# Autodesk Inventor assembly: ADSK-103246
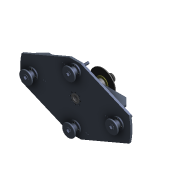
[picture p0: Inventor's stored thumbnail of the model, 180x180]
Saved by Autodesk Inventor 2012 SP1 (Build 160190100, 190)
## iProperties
Shininess: 0.0
Created: 2000-12
Part Number: ADSK-103246
Document SubType Name: Assembly
Designer: gao
Stock Number: ADSK-103246
Density: 0.0
Volumn: 0.0
Area: 0.0
PropertySet Name: Model Information
Control State: 0
Master: False
Checked Out: False
Author: gao
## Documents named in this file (9)
- D:\AOTC\Autodesk Inventor 2012 Essential for New Users\Autodesk Inventor 2012 Essentials - Project Files\Learning\Workspace\Sub-Assemblies\ADSK-103246.iam
- D:\AOTC\Autodesk Inventor 2012 Essential for New Users\Autodesk Inventor 2012 Essentials - Project Files\Learning\Workspace\Parts\ADSK-103455.ipt
- D:\AOTC\Autodesk Inventor 2012 Essential for New Users\Autodesk Inventor 2012 Essentials - Project Files\Learning\Workspace\Parts\ADSK-104069.ipt
- D:\AOTC\Autodesk Inventor 2012 Essential for New Users\Autodesk Inventor 2012 Essentials - Project Files\Learning\Workspace\Parts\ADSK-104065.ipt
- D:\AOTC\Autodesk Inventor 2012 Essential for New Users\Autodesk Inventor 2012 Essentials - Project Files\Learning\Workspace\Sub-Assemblies\ADSK-103223.iam
- D:\AOTC\Autodesk Inventor 2012 Essential for New Users\Autodesk Inventor 2012 Essentials - Project Files\Learning\Workspace\Sub-Assemblies\ADSK-103198.iam
- D:\AOTC\Autodesk Inventor 2012 Essential for New Users\Autodesk Inventor 2012 Essentials - Project Files\Learning\Workspace\Libraries\Content Center Files\en-US\4746AD94-7A15-4D0E-79EA-365386ECB28E.ipt
- D:\AOTC\Autodesk Inventor 2012 Essential for New Users\Autodesk Inventor 2012 Essentials - Project Files\Learning\Workspace\Parts\45665CD9-1C60-DBCA-D3BB-54EB80893890.ipt
- D:\AOTC\Autodesk Inventor 2012 Essential for New Users\Autodesk Inventor 2012 Essentials - Project Files\Learning\Workspace\Parts\F3808AAD-BDC4-3728-F238-65C25E68102C.ipt
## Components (48 placed, 8 different names)
1. ADSK-104069:1 — Insert:1, Insert:2, Insert:3, Insert:4, Insert:5, Insert:24, Insert:25, Insert:26, Insert:27, Insert:28, Insert:29, Insert:30, Insert:31
2. ADSK-103455:1 — Insert:1, Insert:17, Insert:18, Insert:19, Insert:20
3. ADSK-103455:2 — Insert:2, Insert:13, Insert:14, Insert:15, Insert:16
4. ADSK-103455:3 — Insert:3, Insert:9, Insert:10, Insert:11, Insert:12
5. ADSK-103455:4 — Insert:4, Insert:21, Insert:22, Insert:23
6. ADSK-104065:1 — Insert:5, Insert:6, Insert:7
7. ADSK-103223:1 [sub-assembly] — Insert:6
8. ADSK-103198:1 [sub-assembly] — Insert:7
9. Hex Cap Screw - 3/8 - 16 - 1 1/2:1
10. Hex Cap Screw - 3/8 - 16 - 1 1/2:2
11. Hex Cap Screw - 3/8 - 16 - 1 1/2:3 — Insert:22
12. Hex Cap Screw - 3/8 - 16 - 1 1/2:4 — Insert:8
13. Hex Cap Screw - 3/8 - 16 - 1 1/2:5
14. Hex Cap Screw - 3/8 - 16 - 1 1/2:6 — Insert:19
15. Hex Cap Screw - 3/8 - 16 - 1 1/2:7
16. Hex Cap Screw - 3/8 - 16 - 1 1/2:8 — Insert:17
17. Hex Cap Screw - 3/8 - 16 - 1 1/2:9
18. Hex Cap Screw - 3/8 - 16 - 1 1/2:10
19. Hex Cap Screw - 3/8 - 16 - 1 1/2:11
20. Hex Cap Screw - 3/8 - 16 - 1 1/2:12
21. Hex Cap Screw - 3/8 - 16 - 1 1/2:13
22. Hex Cap Screw - 3/8 - 16 - 1 1/2:14
23. Hex Cap Screw - 3/8 - 16 - 1 1/2:15
24. Hex Cap Screw - 3/8 - 16 - 1 1/2:16
25. Helical Spring Lock Washer - 3/8  Regular. Carbon Steel:1 — Insert:20
26. Helical Spring Lock Washer - 3/8  Regular. Carbon Steel:2
27. Helical Spring Lock Washer - 3/8  Regular. Carbon Steel:3 — Insert:18
28. Helical Spring Lock Washer - 3/8  Regular. Carbon Steel:4
29. Helical Spring Lock Washer - 3/8  Regular. Carbon Steel:5 — Insert:21
30. Helical Spring Lock Washer - 3/8  Regular. Carbon Steel:6 — Insert:23
31. Helical Spring Lock Washer - 3/8  Regular. Carbon Steel:7
32. Helical Spring Lock Washer - 3/8  Regular. Carbon Steel:8 — Insert:8
33. Helical Spring Lock Washer - 3/8  Regular. Carbon Steel:9 — Insert:12
34. Helical Spring Lock Washer - 3/8  Regular. Carbon Steel:10 — Insert:11
35. Helical Spring Lock Washer - 3/8  Regular. Carbon Steel:11 — Insert:9
36. Helical Spring Lock Washer - 3/8  Regular. Carbon Steel:12 — Insert:10
37. Helical Spring Lock Washer - 3/8  Regular. Carbon Steel:13 — Insert:13
38. Helical Spring Lock Washer - 3/8  Regular. Carbon Steel:14 — Insert:14
39. Helical Spring Lock Washer - 3/8  Regular. Carbon Steel:15 — Insert:16
40. Helical Spring Lock Washer - 3/8  Regular. Carbon Steel:16 — Insert:15
41. Hexagon Socket Head Cap Screw - 3/8 - 16 - 1 1/2:1 — Insert:30
42. Hexagon Socket Head Cap Screw - 3/8 - 16 - 1 1/2:2 — Insert:29
43. Hexagon Socket Head Cap Screw - 3/8 - 16 - 1 1/2:3 — Insert:28
44. Hexagon Socket Head Cap Screw - 3/8 - 16 - 1 1/2:4 — Insert:24
45. Hexagon Socket Head Cap Screw - 3/8 - 16 - 1 1/2:5 — Insert:25
46. Hexagon Socket Head Cap Screw - 3/8 - 16 - 1 1/2:6 — Insert:26
47. Hexagon Socket Head Cap Screw - 3/8 - 16 - 1 1/2:7 — Insert:27
48. Hexagon Socket Head Cap Screw - 3/8 - 16 - 1 1/2:8 — Insert:31
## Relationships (31: Insert 31)
- Insert:1: ADSK-104069:1 ↔ ADSK-103455:1
- Insert:2: ADSK-104069:1 ↔ ADSK-103455:2
- Insert:3: ADSK-104069:1 ↔ ADSK-103455:3
- Insert:4: ADSK-104069:1 ↔ ADSK-103455:4
- Insert:5: ADSK-104069:1 ↔ ADSK-104065:1
- Insert:6: ADSK-104065:1 ↔ ADSK-103223:1
- Insert:7: ADSK-104065:1 ↔ ADSK-103198:1
- Insert:8: Hex Cap Screw - 3/8 - 16 - 1 1/2:4 ↔ Helical Spring Lock Washer - 3/8  Regular. Carbon Steel:8
- Insert:9: ADSK-103455:3 ↔ Helical Spring Lock Washer - 3/8  Regular. Carbon Steel:11
- Insert:10: ADSK-103455:3 ↔ Helical Spring Lock Washer - 3/8  Regular. Carbon Steel:12
- Insert:11: ADSK-103455:3 ↔ Helical Spring Lock Washer - 3/8  Regular. Carbon Steel:10
- Insert:12: ADSK-103455:3 ↔ Helical Spring Lock Washer - 3/8  Regular. Carbon Steel:9
- Insert:13: ADSK-103455:2 ↔ Helical Spring Lock Washer - 3/8  Regular. Carbon Steel:13
- Insert:14: ADSK-103455:2 ↔ Helical Spring Lock Washer - 3/8  Regular. Carbon Steel:14
- Insert:15: ADSK-103455:2 ↔ Helical Spring Lock Washer - 3/8  Regular. Carbon Steel:16
- Insert:16: ADSK-103455:2 ↔ Helical Spring Lock Washer - 3/8  Regular. Carbon Steel:15
- Insert:17: ADSK-103455:1 ↔ Hex Cap Screw - 3/8 - 16 - 1 1/2:8
- Insert:18: ADSK-103455:1 ↔ Helical Spring Lock Washer - 3/8  Regular. Carbon Steel:3
- Insert:19: ADSK-103455:1 ↔ Hex Cap Screw - 3/8 - 16 - 1 1/2:6
- Insert:20: ADSK-103455:1 ↔ Helical Spring Lock Washer - 3/8  Regular. Carbon Steel:1
- Insert:21: ADSK-103455:4 ↔ Helical Spring Lock Washer - 3/8  Regular. Carbon Steel:5
- Insert:22: ADSK-103455:4 ↔ Hex Cap Screw - 3/8 - 16 - 1 1/2:3
- Insert:23: ADSK-103455:4 ↔ Helical Spring Lock Washer - 3/8  Regular. Carbon Steel:6
- Insert:24: ADSK-104069:1 ↔ Hexagon Socket Head Cap Screw - 3/8 - 16 - 1 1/2:4
- Insert:25: ADSK-104069:1 ↔ Hexagon Socket Head Cap Screw - 3/8 - 16 - 1 1/2:5
- Insert:26: ADSK-104069:1 ↔ Hexagon Socket Head Cap Screw - 3/8 - 16 - 1 1/2:6
- Insert:27: ADSK-104069:1 ↔ Hexagon Socket Head Cap Screw - 3/8 - 16 - 1 1/2:7
- Insert:28: ADSK-104069:1 ↔ Hexagon Socket Head Cap Screw - 3/8 - 16 - 1 1/2:3
- Insert:29: ADSK-104069:1 ↔ Hexagon Socket Head Cap Screw - 3/8 - 16 - 1 1/2:2
- Insert:30: ADSK-104069:1 ↔ Hexagon Socket Head Cap Screw - 3/8 - 16 - 1 1/2:1
- Insert:31: ADSK-104069:1 ↔ Hexagon Socket Head Cap Screw - 3/8 - 16 - 1 1/2:8
